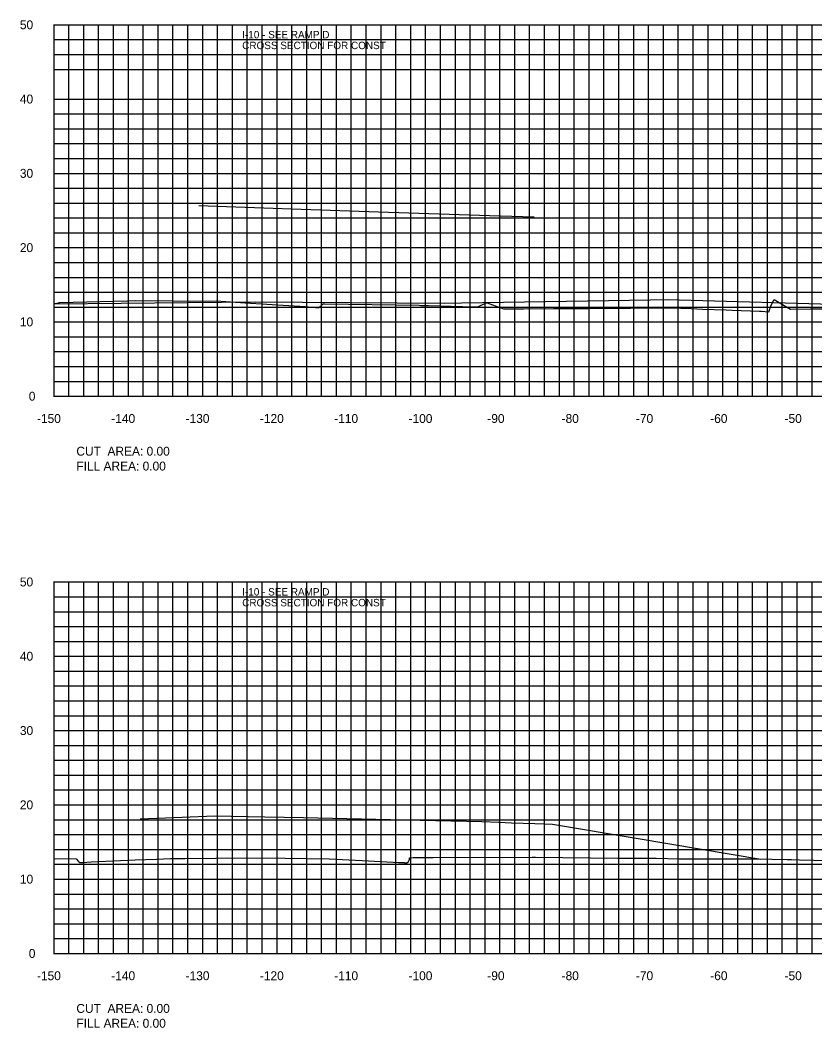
# Model space of a CAD drawing. Extents: x 1800880 to 1814006, y 250083 to 250560.
# Drawn here: x 1809276.4 to 1809383.4, y 250089.4 to 250225 of the extents above; entities that cross this region are included whole.
import ezdxf

# ---------------------------------------------------------------- set-up
doc = ezdxf.new("R2010")
doc.units = 0
for name, color, linetype in [('33', 7, 'Continuous'), ('CL-CNST', 7, 'Continuous'), ('DESIGN - DRAINAGE - Bridges', 7, 'Continuous'), ('DRAINAGETXT', 7, 'Continuous'), ('EPTEXT', 7, 'Continuous'), ('Level 46', 7, 'Continuous'), ('Level 62', 7, 'Continuous')]:
    doc.layers.add(name, color=color, linetype=linetype)

msp = doc.modelspace()

# ---------------------------------------------------------------- linework, layer by layer
at = {"layer": 'CL-CNST'}
for points in [[(1809281, 250186.91), (1809281.03, 250186.91), (1809281.43, 250186.95), (1809281.72, 250187.03), (1809290.89, 250187.26), (1809292.01, 250187.3), (1809301.95, 250187.24), (1809302.83, 250187.25), (1809306.7, 250187), (1809309.64, 250186.81), (1809314.81, 250186.5), (1809316.62, 250186.34), (1809316.65, 250186.33), (1809317.15, 250186.83), (1809317.16, 250186.84), (1809317.17, 250186.85), (1809317.44, 250186.85), (1809330.14, 250186.67), (1809330.3, 250186.66), (1809331.4, 250186.65), (1809337.52, 250186.48), (1809337.61, 250186.48), (1809337.83, 250186.47), (1809338.04, 250186.45), (1809339.14, 250187), (1809339.28, 250187), (1809339.5, 250186.92), (1809341.5, 250186.18), (1809343.62, 250186.19), (1809344.17, 250186.19), (1809348.22, 250186.22), (1809348.95, 250186.22), (1809349.97, 250186.23), (1809352.83, 250186.24), (1809355.76, 250186.27), (1809357.23, 250186.27), (1809357.44, 250186.28), (1809358.55, 250186.29), (1809361.94, 250186.31), (1809362.05, 250186.31), (1809362.37, 250186.31), (1809363.96, 250186.32), (1809366.72, 250186.23), (1809368.25, 250186.17), (1809371.44, 250186.05), (1809372.27, 250186.02), (1809375.92, 250185.87), (1809376.15, 250185.86), (1809377.17, 250185.81), (1809377.49, 250186.69), (1809377.89, 250187.45), (1809379.23, 250186.64), (1809380.11, 250186.17), (1809382.81, 250186.18), (1809384.54, 250186.19)], [(1809281, 250112.2), (1809283.97, 250112.17), (1809284.27, 250111.81), (1809284.43, 250111.66), (1809284.85, 250111.68), (1809285.97, 250111.78), (1809291.91, 250112.01), (1809294.8, 250112.13), (1809296.67, 250112.21), (1809298.59, 250112.23), (1809306.96, 250112.32), (1809312.12, 250112.26), (1809318.01, 250112.15), (1809322.47, 250111.93), (1809326.63, 250111.71), (1809327.37, 250111.68), (1809327.48, 250111.67), (1809327.5, 250111.67), (1809327.74, 250111.67), (1809328, 250111.67), (1809328.02, 250111.67), (1809328.1, 250111.67), (1809328.2, 250111.59), (1809328.33, 250111.62), (1809328.49, 250111.62), (1809328.68, 250111.82), (1809328.85, 250112.08), (1809328.85, 250112.28), (1809329.03, 250112.32), (1809329.04, 250112.32), (1809329.33, 250112.33), (1809330.19, 250112.33), (1809330.65, 250112.33), (1809330.68, 250112.33), (1809330.69, 250112.33), (1809330.69, 250112.33), (1809330.71, 250112.33), (1809331.56, 250112.36), (1809331.97, 250112.36), (1809332, 250112.36), (1809345.32, 250112.38), (1809345.56, 250112.38), (1809345.8, 250112.38), (1809356.87, 250112.27), (1809361.5, 250112.25), (1809361.63, 250112.25), (1809362.01, 250112.25), (1809365.11, 250112.18), (1809375.03, 250112.18), (1809375.09, 250112.18), (1809375.54, 250112.18), (1809379.65, 250112.09), (1809380.22, 250112.08), (1809381.31, 250112.05), (1809387.07, 250111.89)]]:
    msp.add_lwpolyline(points, dxfattribs=at)
at = {"layer": 'DESIGN - DRAINAGE - Bridges'}
for p, q in [((1809280.94, 250224.43), (1809281, 250224.43)), ((1809281, 250174.43), (1809281, 250224.43)), ((1809280.94, 250214.43), (1809281, 250214.43)), ((1809280.94, 250204.43), (1809281, 250204.43)), ((1809280.94, 250194.43), (1809281, 250194.43)), ((1809280.94, 250184.43), (1809281, 250184.43)), ((1809280.94, 250174.43), (1809281, 250174.43)), ((1809281, 250174.43), (1809581, 250174.43)), ((1809281, 250174.37), (1809281, 250174.43)), ((1809291, 250174.37), (1809291, 250174.43)), ((1809301, 250174.37), (1809301, 250174.43)), ((1809311, 250174.37), (1809311, 250174.43)), ((1809321, 250174.37), (1809321, 250174.43)), ((1809331, 250174.37), (1809331, 250174.43)), ((1809341, 250174.37), (1809341, 250174.43)), ((1809351, 250174.37), (1809351, 250174.43)), ((1809361, 250174.37), (1809361, 250174.43)), ((1809371, 250174.37), (1809371, 250174.43)), ((1809381, 250174.37), (1809381, 250174.43)), ((1809280.94, 250149.43), (1809281, 250149.43)), ((1809281, 250099.43), (1809281, 250149.43)), ((1809280.94, 250139.43), (1809281, 250139.43)), ((1809280.94, 250129.43), (1809281, 250129.43)), ((1809280.94, 250119.43), (1809281, 250119.43)), ((1809280.94, 250109.43), (1809281, 250109.43)), ((1809280.94, 250099.43), (1809281, 250099.43)), ((1809281, 250099.43), (1809581, 250099.43)), ((1809281, 250099.37), (1809281, 250099.43)), ((1809291, 250099.37), (1809291, 250099.43)), ((1809301, 250099.37), (1809301, 250099.43)), ((1809311, 250099.37), (1809311, 250099.43)), ((1809321, 250099.37), (1809321, 250099.43)), ((1809331, 250099.37), (1809331, 250099.43)), ((1809341, 250099.37), (1809341, 250099.43)), ((1809351, 250099.37), (1809351, 250099.43)), ((1809361, 250099.37), (1809361, 250099.43)), ((1809371, 250099.37), (1809371, 250099.43)), ((1809381, 250099.37), (1809381, 250099.43))]:
    msp.add_line(p, q, dxfattribs=at)
at = {"layer": 'Level 46'}
for p, q in [((1809281, 250224.43), (1809581, 250224.43)), ((1809281, 250174.43), (1809281, 250224.43)), ((1809283, 250174.43), (1809283, 250224.43)), ((1809285, 250174.43), (1809285, 250224.43)), ((1809287, 250174.43), (1809287, 250224.43)), ((1809289, 250174.43), (1809289, 250224.43)), ((1809291, 250174.43), (1809291, 250224.43)), ((1809293, 250174.43), (1809293, 250224.43)), ((1809295, 250174.43), (1809295, 250224.43)), ((1809297, 250174.43), (1809297, 250224.43)), ((1809299, 250174.43), (1809299, 250224.43)), ((1809301, 250174.43), (1809301, 250224.43)), ((1809303, 250174.43), (1809303, 250224.43)), ((1809305, 250174.43), (1809305, 250224.43)), ((1809307, 250174.43), (1809307, 250224.43)), ((1809309, 250174.43), (1809309, 250224.43)), ((1809311, 250174.43), (1809311, 250224.43)), ((1809313, 250174.43), (1809313, 250224.43)), ((1809315, 250174.43), (1809315, 250224.43)), ((1809317, 250174.43), (1809317, 250224.43)), ((1809319, 250174.43), (1809319, 250224.43)), ((1809321, 250174.43), (1809321, 250224.43)), ((1809323, 250174.43), (1809323, 250224.43)), ((1809325, 250174.43), (1809325, 250224.43)), ((1809327, 250174.43), (1809327, 250224.43)), ((1809329, 250174.43), (1809329, 250224.43)), ((1809331, 250174.43), (1809331, 250224.43)), ((1809333, 250174.43), (1809333, 250224.43)), ((1809335, 250174.43), (1809335, 250224.43)), ((1809337, 250174.43), (1809337, 250224.43)), ((1809339, 250174.43), (1809339, 250224.43)), ((1809341, 250174.43), (1809341, 250224.43)), ((1809343, 250174.43), (1809343, 250224.43)), ((1809345, 250174.43), (1809345, 250224.43)), ((1809347, 250174.43), (1809347, 250224.43)), ((1809349, 250174.43), (1809349, 250224.43)), ((1809351, 250174.43), (1809351, 250224.43)), ((1809353, 250174.43), (1809353, 250224.43)), ((1809355, 250174.43), (1809355, 250224.43)), ((1809357, 250174.43), (1809357, 250224.43)), ((1809359, 250174.43), (1809359, 250224.43)), ((1809361, 250174.43), (1809361, 250224.43)), ((1809363, 250174.43), (1809363, 250224.43)), ((1809365, 250174.43), (1809365, 250224.43)), ((1809367, 250174.43), (1809367, 250224.43)), ((1809369, 250174.43), (1809369, 250224.43)), ((1809371, 250174.43), (1809371, 250224.43)), ((1809373, 250174.43), (1809373, 250224.43)), ((1809375, 250174.43), (1809375, 250224.43)), ((1809377, 250174.43), (1809377, 250224.43)), ((1809379, 250174.43), (1809379, 250224.43)), ((1809381, 250174.43), (1809381, 250224.43)), ((1809383, 250174.43), (1809383, 250224.43)), ((1809281, 250222.43), (1809581, 250222.43)), ((1809281, 250220.43), (1809581, 250220.43)), ((1809281, 250218.43), (1809581, 250218.43)), ((1809281, 250214.43), (1809581, 250214.43)), ((1809281, 250212.43), (1809581, 250212.43)), ((1809281, 250210.43), (1809581, 250210.43)), ((1809281, 250208.43), (1809581, 250208.43)), ((1809281, 250206.43), (1809581, 250206.43)), ((1809281, 250204.43), (1809581, 250204.43)), ((1809281, 250202.43), (1809581, 250202.43)), ((1809281, 250200.43), (1809581, 250200.43)), ((1809281, 250198.43), (1809581, 250198.43)), ((1809281, 250196.43), (1809581, 250196.43)), ((1809281, 250194.43), (1809581, 250194.43)), ((1809281, 250192.43), (1809581, 250192.43)), ((1809281, 250190.43), (1809581, 250190.43)), ((1809281, 250188.43), (1809581, 250188.43)), ((1809281, 250186.43), (1809581, 250186.43)), ((1809281, 250184.43), (1809581, 250184.43)), ((1809281, 250182.43), (1809581, 250182.43)), ((1809281, 250180.43), (1809581, 250180.43)), ((1809281, 250178.43), (1809581, 250178.43)), ((1809281, 250176.43), (1809581, 250176.43)), ((1809281, 250174.43), (1809581, 250174.43)), ((1809281, 250149.43), (1809581, 250149.43)), ((1809281, 250099.43), (1809281, 250149.43)), ((1809283, 250099.43), (1809283, 250149.43)), ((1809285, 250099.43), (1809285, 250149.43)), ((1809287, 250099.43), (1809287, 250149.43)), ((1809289, 250099.43), (1809289, 250149.43)), ((1809291, 250099.43), (1809291, 250149.43)), ((1809293, 250099.43), (1809293, 250149.43)), ((1809295, 250099.43), (1809295, 250149.43)), ((1809297, 250099.43), (1809297, 250149.43)), ((1809299, 250099.43), (1809299, 250149.43)), ((1809301, 250099.43), (1809301, 250149.43)), ((1809303, 250099.43), (1809303, 250149.43)), ((1809305, 250099.43), (1809305, 250149.43)), ((1809307, 250099.43), (1809307, 250149.43)), ((1809309, 250099.43), (1809309, 250149.43)), ((1809311, 250099.43), (1809311, 250149.43)), ((1809313, 250099.43), (1809313, 250149.43)), ((1809315, 250099.43), (1809315, 250149.43)), ((1809317, 250099.43), (1809317, 250149.43)), ((1809319, 250099.43), (1809319, 250149.43)), ((1809321, 250099.43), (1809321, 250149.43)), ((1809323, 250099.43), (1809323, 250149.43)), ((1809325, 250099.43), (1809325, 250149.43)), ((1809327, 250099.43), (1809327, 250149.43)), ((1809329, 250099.43), (1809329, 250149.43)), ((1809331, 250099.43), (1809331, 250149.43)), ((1809333, 250099.43), (1809333, 250149.43)), ((1809335, 250099.43), (1809335, 250149.43)), ((1809337, 250099.43), (1809337, 250149.43)), ((1809339, 250099.43), (1809339, 250149.43)), ((1809341, 250099.43), (1809341, 250149.43)), ((1809343, 250099.43), (1809343, 250149.43)), ((1809345, 250099.43), (1809345, 250149.43)), ((1809347, 250099.43), (1809347, 250149.43)), ((1809349, 250099.43), (1809349, 250149.43)), ((1809351, 250099.43), (1809351, 250149.43)), ((1809353, 250099.43), (1809353, 250149.43)), ((1809355, 250099.43), (1809355, 250149.43)), ((1809357, 250099.43), (1809357, 250149.43)), ((1809359, 250099.43), (1809359, 250149.43)), ((1809361, 250099.43), (1809361, 250149.43)), ((1809363, 250099.43), (1809363, 250149.43)), ((1809365, 250099.43), (1809365, 250149.43)), ((1809367, 250099.43), (1809367, 250149.43)), ((1809369, 250099.43), (1809369, 250149.43)), ((1809371, 250099.43), (1809371, 250149.43)), ((1809373, 250099.43), (1809373, 250149.43)), ((1809375, 250099.43), (1809375, 250149.43)), ((1809377, 250099.43), (1809377, 250149.43)), ((1809379, 250099.43), (1809379, 250149.43)), ((1809381, 250099.43), (1809381, 250149.43)), ((1809383, 250099.43), (1809383, 250149.43)), ((1809281, 250147.43), (1809581, 250147.43)), ((1809281, 250145.43), (1809581, 250145.43)), ((1809281, 250143.43), (1809581, 250143.43)), ((1809281, 250141.43), (1809581, 250141.43)), ((1809281, 250139.43), (1809581, 250139.43)), ((1809281, 250137.43), (1809581, 250137.43)), ((1809281, 250135.43), (1809581, 250135.43)), ((1809281, 250133.43), (1809581, 250133.43)), ((1809281, 250131.43), (1809581, 250131.43)), ((1809281, 250129.43), (1809581, 250129.43)), ((1809281, 250127.43), (1809581, 250127.43)), ((1809281, 250125.43), (1809581, 250125.43)), ((1809281, 250123.43), (1809581, 250123.43)), ((1809281, 250121.43), (1809581, 250121.43)), ((1809281, 250119.43), (1809581, 250119.43)), ((1809281, 250117.43), (1809581, 250117.43)), ((1809281, 250115.43), (1809581, 250115.43)), ((1809281, 250113.43), (1809581, 250113.43)), ((1809281, 250111.43), (1809581, 250111.43)), ((1809281, 250109.43), (1809581, 250109.43)), ((1809281, 250107.43), (1809581, 250107.43)), ((1809281, 250105.43), (1809581, 250105.43)), ((1809281, 250103.43), (1809581, 250103.43)), ((1809281, 250101.43), (1809581, 250101.43)), ((1809281, 250099.43), (1809581, 250099.43))]:
    msp.add_line(p, q, dxfattribs=at)
at = {"layer": 'Level 62'}
for points in [[(1809300.46, 250200.08), (1809305.44, 250199.91), (1809310.5, 250199.74), (1809312.93, 250199.66), (1809315.57, 250199.57), (1809324.66, 250199.26), (1809339.59, 250198.76), (1809344.08, 250198.61), (1809345.59, 250198.56)], [(1809281, 250186.85), (1809308.05, 250187.14), (1809333.53, 250186.97), (1809335.81, 250186.98), (1809361.25, 250187.42), (1809363.56, 250187.43), (1809388.88, 250186.74), (1809389.98, 250186.75)], [(1809292.57, 250117.55), (1809298.22, 250117.78), (1809302.57, 250117.95), (1809309.36, 250117.82), (1809314.57, 250117.72), (1809328.18, 250117.42), (1809338.57, 250117.19), (1809340.85, 250117.1), (1809342.57, 250117.03), (1809345.7, 250116.91), (1809348.07, 250116.81), (1809359.59, 250114.9), (1809376.1, 250112.14)]]:
    msp.add_lwpolyline(points, dxfattribs=at)

# ---------------------------------------------------------------- texts
for s, p in [('-150', (1809278.7, 250170.83)), ('-140', (1809288.7, 250170.83)), ('-130', (1809298.7, 250170.83)), ('-120', (1809308.7, 250170.83)), ('-110', (1809318.7, 250170.83)), ('-100', (1809328.7, 250170.83)), ('-90', (1809339.3, 250170.83)), ('-80', (1809349.3, 250170.83)), ('-70', (1809359.3, 250170.83)), ('-60', (1809369.3, 250170.83)), ('-50', (1809379.3, 250170.83)), ('-150', (1809278.7, 250095.83)), ('-140', (1809288.7, 250095.83)), ('-130', (1809298.7, 250095.83)), ('-120', (1809308.7, 250095.83)), ('-110', (1809318.7, 250095.83)), ('-100', (1809328.7, 250095.83)), ('-90', (1809339.3, 250095.83)), ('-80', (1809349.3, 250095.83)), ('-70', (1809359.3, 250095.83)), ('-60', (1809369.3, 250095.83)), ('-50', (1809379.3, 250095.83))]:
    msp.add_text(s, height=1.2).set_placement(p)
at = {"layer": '33'}
for s, p in [('50', (1809276.4, 250223.83)), ('40', (1809276.4, 250213.83)), ('30', (1809276.4, 250203.83)), ('20', (1809276.4, 250193.83)), ('10', (1809276.4, 250183.83)), ('0', (1809277.6, 250173.83)), ('50', (1809276.4, 250148.83)), ('40', (1809276.4, 250138.83)), ('30', (1809276.4, 250128.83)), ('20', (1809276.4, 250118.83)), ('10', (1809276.4, 250108.83)), ('0', (1809277.6, 250098.83))]:
    msp.add_text(s, height=1.2, dxfattribs=at).set_placement(p)
at = {"layer": 'DESIGN - DRAINAGE - Bridges'}
for p in [(1809281, 250174.43), (1809281, 250099.43)]:
    msp.add_text('-', height=0.0001, dxfattribs=at).set_placement(p)
at = {"layer": 'DRAINAGETXT'}
for s, p in [('CUT  AREA: 0.00', (1809284, 250166.43)), ('FILL AREA: 0.00', (1809284, 250164.43)), ('CUT  AREA: 0.00', (1809284, 250091.43)), ('FILL AREA: 0.00', (1809284, 250089.43))]:
    msp.add_text(s, height=1.2, dxfattribs=at).set_placement(p)
at = {"layer": 'EPTEXT'}
for s, p in [('I-10 - SEE RAMP D', (1809306.32, 250222.6)), ('CROSS SECTION FOR CONST ', (1809306.32, 250221.15)), ('I-10 - SEE RAMP D', (1809306.32, 250147.6)), ('CROSS SECTION FOR CONST ', (1809306.32, 250146.15))]:
    msp.add_text(s, height=1, dxfattribs=at).set_placement(p)

doc.saveas('drawing.dxf')
